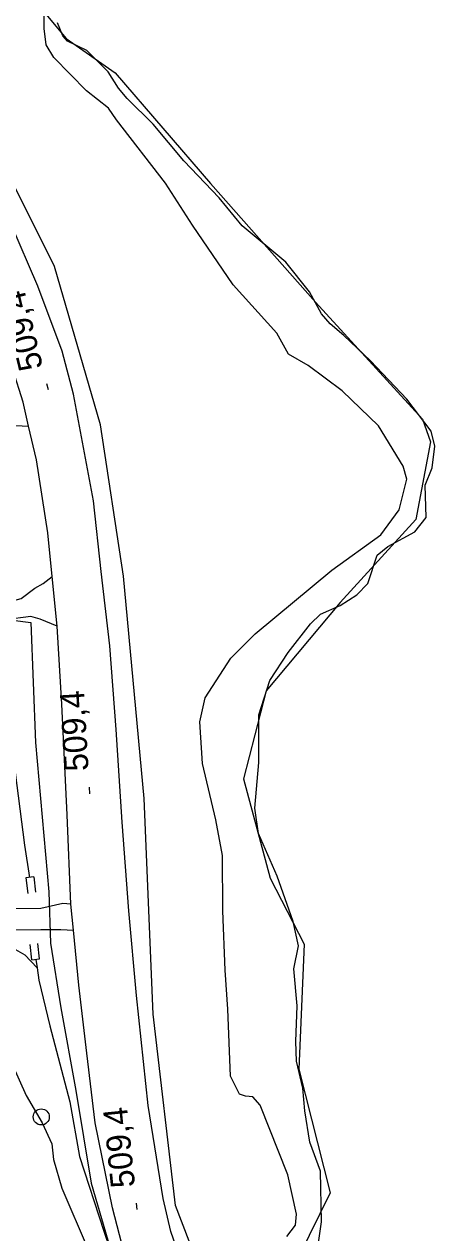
# Model space of a CAD drawing. Extents: x 347059 to 352153, y 6073752 to 6078601.
# Drawn here: x 347909.7 to 347986.1, y 6075328 to 6075553.2 of the extents above; entities that cross this region are included whole.
import ezdxf

# ---------------------------------------------------------------- set-up
doc = ezdxf.new("R2010")
doc.units = 0
for name, color, linetype in [('Level 1', 7, 'Continuous'), ('Level 19', 7, 'Continuous'), ('Level 2', 7, 'Continuous'), ('Level 21', 7, 'Continuous'), ('Level 26', 7, 'Continuous'), ('Level 3', 7, 'Continuous'), ('Level 36', 7, 'Continuous'), ('Level 4', 7, 'Continuous'), ('Level 44', 7, 'Continuous')]:
    doc.layers.add(name, color=color, linetype=linetype)

msp = doc.modelspace()

# ---------------------------------------------------------------- linework, layer by layer
at = {"layer": 'Level 1'}
msp.add_lwpolyline([(347901.1, 6075374.21), (347902.02, 6075367.58), (347905.17, 6075363.6), (347907.26, 6075359.94), (347910.12, 6075353.57), (347913.1, 6075348.5), (347914.87, 6075344.58), (347915.18, 6075341.61), (347916.74, 6075336.32), (347921.63, 6075324.89)], dxfattribs=at)
at = {"layer": 'Level 19'}
for points in [[(347858.72, 6075467.97), (347862.42, 6075470.1), (347865.93, 6075470.85), (347870.29, 6075472.21), (347877.24, 6075474.09), (347886.13, 6075476.28), (347894.81, 6075477.82), (347900.91, 6075478.75), (347904.66, 6075478.63), (347910.54, 6075478.29)], [(347915.85, 6075441.03), (347912.71, 6075442.32), (347910.99, 6075442.82), (347906.21, 6075442.2), (347899.29, 6075440.81), (347893.2, 6075440.12), (347885.23, 6075438.28), (347880.2, 6075438.05), (347874.48, 6075438.69), (347869.48, 6075437.81), (347863.89, 6075436.64), (347862.35, 6075436.15), (347862.09, 6075439.89), (347866.09, 6075440.52), (347871.34, 6075441.55), (347874.08, 6075442.03), (347878.08, 6075443.2), (347884.91, 6075443.46), (347896.32, 6075444.47), (347905.76, 6075445.23), (347909.14, 6075446.16), (347911.73, 6075448.09), (347913.23, 6075449), (347914.94, 6075450.29)], [(347918.4, 6075389.21), (347916.91, 6075389.34), (347912.8, 6075388.4), (347907.26, 6075388.36), (347899.44, 6075387.91), (347893.32, 6075387.76), (347891.21, 6075388.14), (347888.03, 6075388.26), (347885.52, 6075389.02)], [(347885.1, 6075385.29), (347890.01, 6075384.81), (347891.69, 6075384.41), (347897.18, 6075383.59), (347905.5, 6075384.45), (347912.8, 6075384.53), (347916.53, 6075384.49), (347918.88, 6075384.39)]]:
    msp.add_lwpolyline(points, dxfattribs=at)
at = {"layer": 'Level 2'}
msp.add_lwpolyline([(347958.59, 6075327.29), (347960.19, 6075329.42), (347960.39, 6075331.46), (347958.79, 6075338.76), (347953.66, 6075351.77), (347952.26, 6075353.31), (347950.94, 6075353.44), (347949.8, 6075353.84), (347948.12, 6075357.17), (347947.6, 6075369.66), (347947.1, 6075376.92), (347946.67, 6075387.99), (347946.61, 6075398.3), (347945.4, 6075404.96), (347942.91, 6075415.43), (347942.39, 6075423.2), (347943.41, 6075427.66), (347948.17, 6075435.07), (347952.73, 6075439.62), (347967, 6075451.47), (347976.11, 6075458.02), (347979.51, 6075462.69), (347980.94, 6075468.43), (347980.28, 6075470.85), (347975.67, 6075478.36), (347968.9, 6075484.9), (347962.55, 6075489.63), (347958.91, 6075491.7), (347956.77, 6075495.63), (347948.62, 6075504.65), (347941.03, 6075515.74), (347936.02, 6075523.57), (347926.88, 6075535.4), (347925.39, 6075537.53), (347921.34, 6075540.78), (347915.22, 6075547.02), (347913.82, 6075549.36), (347913.45, 6075552.41), (347913.46, 6075554.83)], dxfattribs=at)
at = {"layer": 'Level 21'}
for points in [[(347941.2, 6075316.25), (347937, 6075328.23), (347935.59, 6075334.4), (347932.81, 6075351.71), (347930.64, 6075372.21), (347929.21, 6075387.95), (347927.96, 6075404.53), (347926.82, 6075421.8), (347925.66, 6075437.39), (347924.05, 6075451.21), (347922.63, 6075464.36), (347918.91, 6075484.27), (347916.77, 6075492.24), (347912.26, 6075504.4), (347907.22, 6075516.03), (347902.55, 6075527.13), (347896.05, 6075540.01), (347889.15, 6075552.39), (347881.75, 6075567.37), (347873.12, 6075581.15), (347863.75, 6075595.87)], [(347929.65, 6075319.22), (347926.19, 6075332.66), (347922.95, 6075348.47), (347921.38, 6075361.45), (347919.91, 6075374.14), (347918.88, 6075384.39), (347918.4, 6075389.21), (347917.7, 6075405.85), (347916.74, 6075426.5), (347915.85, 6075441.03), (347914.94, 6075450.29), (347914.15, 6075458.42), (347912.01, 6075471.99), (347910.54, 6075478.29), (347909.51, 6075482.76), (347907.61, 6075488.88), (347906.98, 6075490.93), (347900.16, 6075509.76), (347890.68, 6075529.66), (347884.08, 6075542.3), (347878.04, 6075553.06)]]:
    msp.add_lwpolyline(points, dxfattribs=at)
at = {"layer": 'Level 26'}
for p, q in [((347911.49, 6075394.29), (347910.03, 6075394.1)), ((347910.03, 6075394.1), (347910.41, 6075391.23)), ((347911.49, 6075394.29), (347911.83, 6075391.43)), ((347911.12, 6075378.85), (347910.82, 6075381.71)), ((347912.57, 6075379.01), (347912.26, 6075381.88)), ((347911.12, 6075378.85), (347912.57, 6075379.01))]:
    msp.add_line(p, q, dxfattribs=at)
at = {"layer": 'Level 3'}
for p, q in [((347914.22, 6075485.04), (347913.94, 6075486.21)), ((347921.93, 6075409.8), (347921.85, 6075411)), ((347930.77, 6075332.3), (347930.65, 6075333.49))]:
    msp.add_line(p, q, dxfattribs=at)
at = {"layer": 'Level 36'}
msp.add_circle((347912.9, 6075349.57), 1.5, dxfattribs=at)
at = {"layer": 'Level 4'}
for points in [[(347962.85, 6075503.35), (347958.44, 6075508.84), (347950.29, 6075515.6), (347946.02, 6075520.84), (347939.43, 6075527.72), (347933.73, 6075534.54), (347928.86, 6075539.34), (347927.29, 6075541.26), (347925.35, 6075544.31), (347921.4, 6075548.3), (347917.77, 6075550.05), (347916.91, 6075551.05), (347915.91, 6075553.46)], [(347964.47, 6075326.14), (347965.07, 6075330.04), (347964.9, 6075339.47), (347962.89, 6075344.87), (347961.94, 6075350.71), (347961.58, 6075354.93), (347960.4, 6075359.97), (347960.31, 6075363.6), (347960.55, 6075370.28), (347959.91, 6075377.2), (347960.79, 6075381.48), (347959.8, 6075386.01), (347956.83, 6075394.46), (347953.32, 6075402.38), (347952.63, 6075407.08), (347953.41, 6075415.65), (347953.4, 6075424.53), (347955.41, 6075430.89), (347958.85, 6075436.09), (347962.99, 6075441.44), (347964.88, 6075443.24), (347968.52, 6075444.85), (347971.66, 6075446.87), (347973.66, 6075449), (347975.41, 6075454.23), (347977.42, 6075455.9), (347982.43, 6075458.58), (347984.56, 6075461.26), (347984.37, 6075467.28), (347985.65, 6075470.54), (347986.14, 6075474.57), (347985.45, 6075477.39), (347980.94, 6075483.34), (347974.18, 6075490.44), (347969.19, 6075495.16), (347966.69, 6075497.36), (347965.08, 6075499.25), (347962.85, 6075503.35)], [(347905.06, 6075437.83), (347905.43, 6075433.5), (347906.56, 6075424.58), (347908.05, 6075413.73), (347909.76, 6075400.23), (347910.74, 6075394.22)], [(347837.6, 6075373.65), (347841.65, 6075375.54), (347845.66, 6075376.94), (347851.67, 6075377.31), (347857.55, 6075376.74), (347863.54, 6075377.31), (347872.05, 6075378.11), (347880.82, 6075379.5), (347890.37, 6075380.04), (347902.37, 6075381.71), (347906.83, 6075381.52), (347909.83, 6075379.81), (347912.11, 6075377.34)], [(347911.87, 6075378.91), (347912.11, 6075377.34), (347912.44, 6075375.06), (347914.51, 6075366.54), (347918.23, 6075352.39), (347920.03, 6075342.22), (347924.54, 6075328.29), (347927.85, 6075318.59), (347932.35, 6075307.77), (347935.71, 6075300.34)]]:
    msp.add_lwpolyline(points, dxfattribs=at)
at = {"layer": 'Level 44'}
for points in [[(347950.56, 6075412.59), (347955.53, 6075394.04), (347961.8, 6075381.79), (347960.86, 6075358.45), (347966.64, 6075335.42), (347956.96, 6075315.59), (347954.08, 6075303.85), (347948.34, 6075305.68), (347937.86, 6075333.06), (347933.71, 6075368.72), (347932.03, 6075408.9), (347928.21, 6075450.33), (347923.9, 6075478.55), (347915.36, 6075508.03), (347894.9, 6075549.01), (347872.97, 6075582.7), (347845.07, 6075625.82), (347811.9, 6075672.62), (347794.35, 6075704.83)], [(347845.71, 6075683.42), (347836.37, 6075667.79), (347837.43, 6075658.07), (347848.38, 6075647.42), (347858.75, 6075626.84), (347866.86, 6075615.27), (347872.31, 6075607.49), (347882.47, 6075594.94), (347891.73, 6075583.44), (347902.22, 6075570.87), (347909.42, 6075560.34), (347917.51, 6075550.56), (347926.66, 6075544.14), (347944.37, 6075523.49), (347963.94, 6075501.4), (347983.85, 6075479.6), (347985.33, 6075475.4), (347982.61, 6075460.88), (347968.54, 6075445.42), (347954.73, 6075428.96), (347950.56, 6075412.59)], [(347907.57, 6075442.12), (347910.97, 6075441.7), (347911.81, 6075419.32), (347914.28, 6075391.51), (347914.61, 6075381.93), (347916.57, 6075369.92), (347919.32, 6075354.51), (347922.18, 6075337.2), (347929.58, 6075311.94)]]:
    msp.add_lwpolyline(points, dxfattribs=at)

# ---------------------------------------------------------------- texts
at = {"layer": 'Level 3'}
for rotation, p in [(103.6069, (347913.26, 6075489.24)), (93.3523, (347921.72, 6075414.12)), (95.8352, (347930.38, 6075336.6))]:
    msp.add_text('509,4', height=4.5, rotation=rotation, dxfattribs=at).set_placement(p)

doc.saveas('drawing.dxf')
